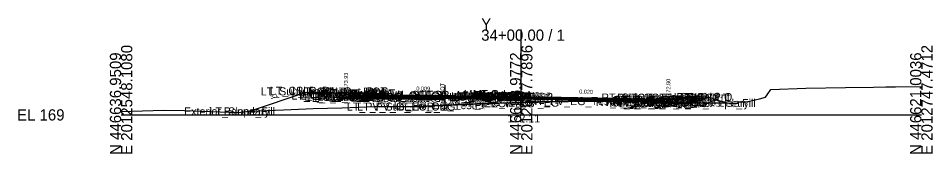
# Model space of a CAD drawing. Extents: x -26 to 3203, y -10 to 9532.
# Drawn here: x 1974.3 to 2202.8, y 7990.3 to 8024.1 of the extents above; entities that cross this region are included whole.
import ezdxf

# ---------------------------------------------------------------- set-up
doc = ezdxf.new("R2010")
doc.units = 0
for name, color, linetype in [('Default', 7, 'Continuous'), ('Exist CMT Pavement', 7, 'Continuous'), ('Exist Cross Section Cell', 7, 'Continuous'), ('Exist XS Center Line Elevation Label', 7, 'Continuous'), ('Exist XS Ground Line', 7, 'Continuous'), ('Prop CMT Conc Surface', 7, 'Continuous'), ('Prop CMT Concrete Structures', 7, 'Continuous'), ('Prop CMT Pvmt Course 1', 7, 'Continuous'), ('Prop CMT Pvmt Course 1 CG', 7, 'Continuous'), ('Prop CMT Pvmt Course 1 Wedge', 7, 'Continuous'), ('Prop CMT Pvmt Course 2', 7, 'Continuous'), ('Prop CMT Pvmt Course 2 Wedge', 7, 'Continuous'), ('Prop CMT Pvmt Course 3', 7, 'Continuous'), ('Prop CMT Pvmt Course 3 Wedge', 7, 'Continuous'), ('Prop CMT Pvmt Surface', 7, 'Continuous'), ('Prop CMT Pvmt Wedge Surface 1', 7, 'Continuous'), ('Prop CMT Pvmt Wedge Surface 2', 7, 'Continuous'), ('Prop CMT Pvmt Wedge Surface 3', 7, 'Continuous'), ('Prop CMT Slope Grass', 7, 'Continuous'), ('Prop CMT Subgrade Earthwork', 7, 'Continuous'), ('Prop XS Hydro Elevations', 7, 'Continuous'), ('Prop XS Label Text', 7, 'Continuous'), ('Prop XS SE Text', 7, 'Continuous'), ('Prop XS Side Slope Text', 7, 'Continuous'), ('Scratch_Level_0', 7, 'Continuous')]:
    doc.layers.add(name, color=color, linetype=linetype)

msp = doc.modelspace()

# ---------------------------------------------------------------- linework, layer by layer
at = {"layer": 'Exist CMT Pavement'}
for points in [[(2115.72, 8003.44), (2097.68, 8003.05)], [(2132.75, 8003.24), (2115.72, 8003.44)], [(2080.92, 8002.42), (2081.73, 8002.44)], [(2081.73, 8002.44), (2092, 8002.89)]]:
    msp.add_lwpolyline(points, dxfattribs=at)
at = {"layer": 'Exist Cross Section Cell'}
for p, q in [((2100, 8000), (2100, 8021.33)), ((2000, 8000), (2100, 8000)), ((2100, 8000), (2200, 8000))]:
    msp.add_line(p, q, dxfattribs=at)
at = {"layer": 'Exist XS Ground Line'}
msp.add_lwpolyline([(2000, 8000.86), (2010.69, 8001.21), (2015.84, 8001.06), (2029.2, 8000.59), (2031.35, 8000.86), (2032.14, 8000.9), (2040.62, 8001.23), (2046.25, 8001.55), (2048.04, 8001.59), (2055.14, 8001.79), (2063.36, 8002.12), (2065.93, 8002.07), (2071.46, 8002.09), (2072.32, 8001.98), (2078.4, 8002.3), (2079.94, 8002.36), (2080.49, 8002.39), (2080.91, 8002.41), (2082.43, 8002.47), (2084.3, 8002.58), (2084.78, 8002.6), (2086.07, 8002.7), (2086.69, 8002.71), (2089.2, 8002.8), (2091.32, 8002.87), (2091.72, 8002.88), (2093.65, 8002.95), (2094.23, 8002.97), (2094.9, 8002.98), (2096.73, 8003.03), (2097.63, 8003.05), (2099.22, 8003.09), (2100, 8003.11), (2100.59, 8003.13), (2101.72, 8003.15), (2103.05, 8003.19), (2104.21, 8003.21), (2105.21, 8003.24), (2106.72, 8003.28), (2108.49, 8003.31), (2109.23, 8003.33), (2109.86, 8003.34), (2111.73, 8003.38), (2114.27, 8003.42), (2116.71, 8003.45), (2117.45, 8003.45), (2119.27, 8003.46), (2121.82, 8003.46), (2122.15, 8003.46), (2124.34, 8003.44), (2124.93, 8003.43), (2126.84, 8003.39), (2128.49, 8003.35), (2129.35, 8003.33), (2130.36, 8003.3), (2131.85, 8003.26), (2133.08, 8003.24), (2134.36, 8003.22), (2135.45, 8003.2), (2136.86, 8003.17), (2138.51, 8003.14), (2139.37, 8003.13), (2141.23, 8003.1), (2141.86, 8003.09), (2143.95, 8003.05), (2144.36, 8003.05), (2146.86, 8003.01), (2148.93, 8003), (2149.46, 8002.99), (2151.93, 8002.95), (2152.41, 8002.92), (2153.69, 8002.85), (2154.41, 8003.28), (2154.89, 8003.3), (2156.33, 8003.29), (2159.52, 8004.02), (2161.08, 8004.43), (2161.46, 8004.98), (2162.42, 8006.38), (2171.11, 8006.64), (2181.06, 8006.88), (2188.08, 8006.97), (2191.1, 8006.99), (2193.51, 8007.03), (2200, 8007.11)], dxfattribs=at)
at = {"layer": 'Prop CMT Conc Surface'}
for points in [[(2051.69, 8005.52), (2046.69, 8005.62)], [(2056.19, 8004.93), (2056.19, 8005.43), (2055.69, 8005.43)], [(2058.19, 8004.99), (2056.19, 8004.93)], [(2134.75, 8003.92), (2136.75, 8003.8)], [(2136.75, 8003.8), (2136.75, 8004.3), (2137.25, 8004.3)], [(2141.25, 8004.39), (2146.25, 8004.49)]]:
    msp.add_lwpolyline(points, dxfattribs=at)
at = {"layer": 'Prop CMT Concrete Structures'}
for points in [[(2046.69, 8005.29), (2046.69, 8005.62)], [(2046.69, 8005.62), (2051.69, 8005.52)], [(2051.69, 8005.52), (2051.69, 8005.19)], [(2051.69, 8005.19), (2046.69, 8005.29)], [(2058.19, 8004.99), (2056.19, 8004.93), (2056.19, 8005.43), (2055.69, 8005.43)], [(2055.69, 8005.43), (2055.69, 8004.43), (2058.19, 8004.41)], [(2058.19, 8004.41), (2058.19, 8004.99)], [(2097.68, 8004.66), (2097.67, 8004.83), (2096.92, 8005.08), (2094.84, 8005.14), (2092.76, 8005.1), (2092.01, 8004.85), (2092, 8004.69)], [(2092, 8004.69), (2097.68, 8004.66)], [(2134.75, 8003.92), (2136.75, 8003.8), (2136.75, 8004.3), (2137.25, 8004.3)], [(2137.25, 8004.3), (2137.25, 8003.28), (2134.75, 8003.33)], [(2134.75, 8003.33), (2134.75, 8003.92)], [(2146.25, 8004.49), (2141.25, 8004.39)], [(2141.25, 8004.39), (2141.25, 8004.05)], [(2141.25, 8004.05), (2146.25, 8004.15)], [(2146.25, 8004.15), (2146.25, 8004.49)]]:
    msp.add_lwpolyline(points, dxfattribs=at)
at = {"layer": 'Prop CMT Pvmt Course 1'}
for points in [[(2092, 8004.69), (2058.19, 8004.99)], [(2058.19, 8004.99), (2058.19, 8004.74)], [(2058.19, 8004.74), (2071.46, 8004.62)], [(2071.46, 8004.62), (2071.46, 8004.75)], [(2071.46, 8004.75), (2092, 8004.56)], [(2080.91, 8004.72), (2080.91, 8004.84)], [(2092, 8004.69), (2097.68, 8004.66)], [(2092, 8004.44), (2092, 8004.69)], [(2092, 8004.44), (2092, 8004.69)], [(2092, 8004.56), (2092, 8004.44), (2092, 8004.44)], [(2097.68, 8004.41), (2092, 8004.44)], [(2097.68, 8004.66), (2134.75, 8003.92)], [(2097.68, 8004.41), (2097.68, 8004.66)], [(2097.68, 8004.66), (2097.68, 8004.41)], [(2132.75, 8003.83), (2097.68, 8004.53)], [(2097.68, 8004.53), (2097.68, 8004.41), (2097.68, 8004.41)], [(2132.75, 8003.71), (2132.75, 8003.83)], [(2134.75, 8003.67), (2133.75, 8003.69)], [(2134.75, 8003.92), (2134.75, 8003.67)]]:
    msp.add_lwpolyline(points, dxfattribs=at)
at = {"layer": 'Prop CMT Pvmt Course 1 CG'}
for points in [[(2058.19, 8004.41), (2055.19, 8004.44), (2054.86, 8004.11)], [(2054.86, 8004.11), (2058.19, 8004.08)], [(2058.19, 8004.08), (2058.19, 8004.41)], [(2134.75, 8003.33), (2137.75, 8003.27), (2138.09, 8002.93)], [(2134.75, 8003), (2134.75, 8003.33)], [(2138.09, 8002.93), (2134.75, 8003)]]:
    msp.add_lwpolyline(points, dxfattribs=at)
at = {"layer": 'Prop CMT Pvmt Course 1 Wedge'}
for points in [[(2071.46, 8004.75), (2071.46, 8004.75)], [(2071.46, 8004.75), (2072.13, 8004.74), (2072.32, 8004.74), (2078.4, 8004.68), (2079.94, 8004.67), (2080.49, 8004.67), (2080.91, 8004.66), (2082.42, 8004.65), (2082.43, 8004.65), (2084.3, 8004.63), (2084.78, 8004.63), (2086.07, 8004.61), (2086.68, 8004.61), (2086.69, 8004.61), (2088.99, 8004.59), (2089.2, 8004.59), (2091.32, 8004.57), (2091.72, 8004.56), (2092, 8004.56)], [(2071.46, 8004.62), (2071.46, 8004.75)], [(2092, 8004.44), (2091.72, 8004.44), (2091.32, 8004.44), (2089.2, 8004.46), (2088.99, 8004.46), (2086.69, 8004.48), (2086.68, 8004.48), (2086.07, 8004.49), (2084.78, 8004.5), (2084.3, 8004.51), (2082.43, 8004.52), (2082.42, 8004.52), (2080.91, 8004.54), (2080.49, 8004.54), (2079.94, 8004.55), (2078.4, 8004.56), (2072.32, 8004.62), (2072.13, 8004.62), (2071.46, 8004.62)], [(2071.46, 8004.62), (2071.46, 8004.62)], [(2092, 8004.56), (2092, 8004.44)], [(2097.68, 8004.41), (2097.68, 8004.53)], [(2097.68, 8004.53), (2099.22, 8004.5), (2100.59, 8004.48), (2101.72, 8004.45), (2103.05, 8004.43), (2104.21, 8004.4), (2105.21, 8004.38), (2106.72, 8004.35), (2108.49, 8004.32), (2109.23, 8004.3), (2109.86, 8004.29), (2111.73, 8004.25), (2113.99, 8004.21), (2114.27, 8004.2), (2116.65, 8004.15), (2116.71, 8004.15), (2117.45, 8004.14), (2119.15, 8004.1), (2119.27, 8004.1), (2121.53, 8004.06), (2121.82, 8004.05), (2122.15, 8004.04), (2124.34, 8004), (2124.93, 8003.99), (2126.84, 8003.95), (2128.49, 8003.92), (2129.35, 8003.9), (2130.36, 8003.88), (2131.85, 8003.85), (2132.75, 8003.83)], [(2133.75, 8003.69), (2133.08, 8003.7), (2131.85, 8003.73), (2130.36, 8003.76), (2129.35, 8003.78), (2128.49, 8003.79), (2126.84, 8003.83), (2124.93, 8003.86), (2124.34, 8003.88), (2122.15, 8003.92), (2121.82, 8003.93), (2121.53, 8003.93), (2119.27, 8003.98), (2119.15, 8003.98), (2117.45, 8004.01), (2116.71, 8004.03), (2116.65, 8004.03), (2114.27, 8004.08), (2113.99, 8004.08), (2111.73, 8004.13), (2109.86, 8004.17), (2109.23, 8004.18), (2108.49, 8004.19), (2106.72, 8004.23), (2105.21, 8004.26), (2104.21, 8004.28), (2103.05, 8004.3), (2101.72, 8004.33), (2100.59, 8004.35), (2099.22, 8004.38), (2097.68, 8004.41)], [(2132.75, 8003.83), (2132.75, 8003.71)]]:
    msp.add_lwpolyline(points, dxfattribs=at)
at = {"layer": 'Prop CMT Pvmt Course 2'}
for points in [[(2071.46, 8004.62), (2058.19, 8004.74)], [(2058.19, 8004.74), (2058.19, 8004.41)], [(2058.19, 8004.41), (2071.46, 8004.29)], [(2071.46, 8004.29), (2071.46, 8004.62)], [(2080.91, 8004.38), (2080.91, 8004.72)], [(2092, 8004.44), (2097.68, 8004.41)], [(2092, 8004.1), (2092, 8004.44)], [(2097.68, 8004.08), (2092, 8004.1)], [(2097.68, 8004.41), (2097.68, 8004.08)], [(2132.75, 8003.37), (2132.75, 8003.71)], [(2133.75, 8003.69), (2134.75, 8003.67)], [(2134.75, 8003.33), (2133.75, 8003.35)], [(2134.75, 8003.67), (2134.75, 8003.33)]]:
    msp.add_lwpolyline(points, dxfattribs=at)
at = {"layer": 'Prop CMT Pvmt Course 2 Wedge'}
for points in [[(2071.46, 8004.62), (2071.46, 8004.62)], [(2071.46, 8004.62), (2072.13, 8004.62), (2072.32, 8004.62), (2078.4, 8004.56), (2079.94, 8004.55), (2080.49, 8004.54), (2080.91, 8004.54), (2082.42, 8004.52), (2082.43, 8004.52), (2084.3, 8004.51), (2084.78, 8004.5), (2086.07, 8004.49), (2086.68, 8004.48), (2086.69, 8004.48), (2088.99, 8004.46), (2089.2, 8004.46), (2091.32, 8004.44), (2091.72, 8004.44), (2092, 8004.44)], [(2071.46, 8004.29), (2071.46, 8004.62)], [(2092, 8004.1), (2091.72, 8004.11), (2091.32, 8004.11), (2089.2, 8004.13), (2088.99, 8004.13), (2086.69, 8004.15), (2086.68, 8004.15), (2086.07, 8004.16), (2084.78, 8004.17), (2084.3, 8004.17), (2082.43, 8004.19), (2082.42, 8004.19), (2080.91, 8004.2), (2080.49, 8004.21), (2079.94, 8004.21), (2078.4, 8004.23), (2072.32, 8004.28), (2072.13, 8004.28), (2071.46, 8004.29)], [(2071.46, 8004.29), (2071.46, 8004.29)], [(2092, 8004.44), (2092, 8004.1)], [(2097.68, 8004.41), (2099.22, 8004.38), (2100.59, 8004.35), (2101.72, 8004.33), (2103.05, 8004.3), (2104.21, 8004.28), (2105.21, 8004.26), (2106.72, 8004.23), (2108.49, 8004.19), (2109.23, 8004.18), (2109.86, 8004.17), (2111.73, 8004.13), (2113.99, 8004.08), (2114.27, 8004.08), (2116.65, 8004.03), (2116.71, 8004.03), (2117.45, 8004.01), (2119.15, 8003.98), (2119.27, 8003.98), (2121.53, 8003.93), (2121.82, 8003.93), (2122.15, 8003.92), (2124.34, 8003.88), (2124.93, 8003.86), (2126.84, 8003.83), (2128.49, 8003.79), (2129.35, 8003.78), (2130.36, 8003.76), (2131.85, 8003.73), (2133.08, 8003.7), (2133.75, 8003.69)], [(2097.68, 8004.08), (2097.68, 8004.41)], [(2133.75, 8003.35), (2133.08, 8003.37), (2131.85, 8003.39), (2130.36, 8003.42), (2129.35, 8003.44), (2128.49, 8003.46), (2126.84, 8003.49), (2124.93, 8003.53), (2124.34, 8003.54), (2122.15, 8003.59), (2121.82, 8003.59), (2121.53, 8003.6), (2119.27, 8003.64), (2119.15, 8003.65), (2117.45, 8003.68), (2116.71, 8003.7), (2116.65, 8003.7), (2114.27, 8003.74), (2113.99, 8003.75), (2111.73, 8003.79), (2109.86, 8003.83), (2109.23, 8003.84), (2108.49, 8003.86), (2106.72, 8003.9), (2105.21, 8003.93), (2104.21, 8003.95), (2103.05, 8003.97), (2101.72, 8004), (2100.59, 8004.02), (2099.22, 8004.04), (2097.68, 8004.08)], [(2132.75, 8003.71), (2132.75, 8003.37)]]:
    msp.add_lwpolyline(points, dxfattribs=at)
at = {"layer": 'Prop CMT Pvmt Course 3'}
for points in [[(2071.46, 8004.29), (2058.19, 8004.41)], [(2058.19, 8004.41), (2058.19, 8004.08)], [(2058.19, 8004.08), (2080.91, 8003.87)], [(2071.46, 8003.96), (2071.46, 8004.29)], [(2080.91, 8004.05), (2080.91, 8004.38)], [(2092, 8004.1), (2097.68, 8004.08)], [(2133.75, 8003.35), (2134.75, 8003.33)], [(2134.75, 8003.33), (2134.75, 8003)], [(2134.75, 8003), (2132.75, 8003.04)]]:
    msp.add_lwpolyline(points, dxfattribs=at)
at = {"layer": 'Prop CMT Pvmt Course 3 Wedge'}
for points in [[(2071.46, 8004.29), (2071.46, 8004.29)], [(2071.46, 8004.29), (2072.13, 8004.28), (2072.32, 8004.28), (2078.4, 8004.23), (2079.94, 8004.21), (2080.49, 8004.21), (2080.91, 8004.2), (2082.42, 8004.19), (2082.43, 8004.19), (2084.3, 8004.17), (2084.78, 8004.17), (2086.07, 8004.16), (2086.68, 8004.15), (2086.69, 8004.15), (2088.99, 8004.13), (2089.2, 8004.13), (2091.32, 8004.11), (2091.72, 8004.11), (2092, 8004.1)], [(2097.68, 8004.08), (2099.22, 8004.04), (2100.59, 8004.02), (2101.72, 8004), (2103.05, 8003.97), (2104.21, 8003.95), (2105.21, 8003.93), (2106.72, 8003.9), (2108.49, 8003.86), (2109.23, 8003.84), (2109.86, 8003.83), (2111.73, 8003.79), (2113.99, 8003.75), (2114.27, 8003.74), (2116.65, 8003.7), (2116.71, 8003.7), (2117.45, 8003.68), (2119.15, 8003.65), (2119.27, 8003.64), (2121.53, 8003.6), (2121.82, 8003.59), (2122.15, 8003.59), (2124.34, 8003.54), (2124.93, 8003.53), (2126.84, 8003.49), (2128.49, 8003.46), (2129.35, 8003.44), (2130.36, 8003.42), (2131.85, 8003.39), (2133.08, 8003.37), (2133.75, 8003.35)], [(2133.75, 8003.23), (2133.08, 8003.24), (2131.85, 8003.26), (2130.36, 8003.3), (2129.35, 8003.33), (2128.49, 8003.35), (2126.84, 8003.39), (2124.93, 8003.43), (2124.34, 8003.44), (2122.15, 8003.46), (2121.82, 8003.46), (2121.53, 8003.46), (2119.27, 8003.46), (2119.15, 8003.46), (2117.45, 8003.45), (2116.71, 8003.45), (2116.65, 8003.45), (2114.27, 8003.42), (2113.99, 8003.41), (2111.73, 8003.38), (2109.86, 8003.34), (2109.23, 8003.33), (2108.49, 8003.31), (2106.72, 8003.28), (2105.21, 8003.24), (2104.21, 8003.21), (2103.05, 8003.19), (2101.72, 8003.15), (2100.59, 8003.13), (2099.22, 8003.09), (2097.68, 8003.05)], [(2132.75, 8003.37), (2132.75, 8003.25)], [(2092, 8002.89), (2091.72, 8002.88), (2091.32, 8002.87), (2089.2, 8002.8), (2088.99, 8002.79), (2086.69, 8002.71), (2086.68, 8002.71), (2086.07, 8002.7), (2084.78, 8002.6), (2084.3, 8002.58), (2082.43, 8002.47), (2082.42, 8002.47), (2080.91, 8002.41), (2080.49, 8002.39), (2079.94, 8002.36), (2078.4, 8002.3), (2072.32, 8001.98), (2072.13, 8001.99), (2071.46, 8002.09)], [(2071.46, 8002.09), (2071.46, 8002.09)]]:
    msp.add_lwpolyline(points, dxfattribs=at)
at = {"layer": 'Prop CMT Pvmt Surface'}
for points in [[(2092, 8004.69), (2058.19, 8004.99)], [(2092, 8004.69), (2097.68, 8004.66)], [(2097.68, 8004.66), (2134.75, 8003.92)]]:
    msp.add_lwpolyline(points, dxfattribs=at)
at = {"layer": 'Prop CMT Pvmt Wedge Surface 1'}
for points in [[(2058.19, 8004.74), (2058.19, 8004.99)], [(2071.46, 8004.62), (2058.19, 8004.74)], [(2092, 8004.56), (2071.46, 8004.75)], [(2071.46, 8004.75), (2071.46, 8004.62)], [(2080.91, 8004.84), (2080.91, 8004.72)], [(2092, 8004.69), (2092, 8004.44), (2092, 8004.44), (2092, 8004.56)], [(2097.68, 8004.66), (2097.68, 8004.41), (2097.68, 8004.41), (2097.68, 8004.53)], [(2097.68, 8004.53), (2132.75, 8003.83)], [(2132.75, 8003.83), (2132.75, 8003.71)], [(2133.75, 8003.69), (2134.75, 8003.67)], [(2134.75, 8003.67), (2134.75, 8003.92)]]:
    msp.add_lwpolyline(points, dxfattribs=at)
at = {"layer": 'Prop CMT Pvmt Wedge Surface 2'}
for points in [[(2058.19, 8004.74), (2058.19, 8004.99)], [(2092, 8004.44), (2058.19, 8004.74)], [(2092, 8004.69), (2092, 8004.44)], [(2097.68, 8004.66), (2097.68, 8004.41)], [(2097.68, 8004.41), (2134.75, 8003.67)], [(2134.75, 8003.67), (2134.75, 8003.92)]]:
    msp.add_lwpolyline(points, dxfattribs=at)
at = {"layer": 'Prop CMT Pvmt Wedge Surface 3'}
for points in [[(2058.19, 8004.41), (2058.19, 8004.99)], [(2092, 8004.1), (2058.19, 8004.41)], [(2092, 8004.69), (2092, 8004.1)], [(2097.68, 8004.66), (2097.68, 8004.08)], [(2097.68, 8004.08), (2134.75, 8003.33)], [(2134.75, 8003.33), (2134.75, 8003.92)]]:
    msp.add_lwpolyline(points, dxfattribs=at)
at = {"layer": 'Prop CMT Slope Grass'}
for points in [[(2055.69, 8005.43), (2046.19, 8005.62), (2031.99, 8000.89)], [(2137.25, 8004.3), (2146.25, 8004.48)], [(2146.25, 8004.48), (2146.75, 8004.49), (2151.33, 8002.96)]]:
    msp.add_lwpolyline(points, dxfattribs=at)
at = {"layer": 'Prop CMT Subgrade Earthwork'}
msp.add_line((2132.75, 8003.24), (2132.75, 8003.04), dxfattribs=at)
for points in [[(2058.19, 8004.08), (2054.86, 8004.11), (2053.49, 8005.48)], [(2080.91, 8003.87), (2058.19, 8004.08)], [(2080.91, 8003.87), (2080.92, 8002.42)], [(2134.75, 8003), (2138.09, 8002.93), (2139.5, 8004.34)], [(2132.75, 8003.04), (2134.75, 8003)]]:
    msp.add_lwpolyline(points, dxfattribs=at)
at = {"layer": 'Prop XS Label Text'}
msp.add_line((2080.91, 8007.41), (2080.91, 8002.41), dxfattribs=at)

# ---------------------------------------------------------------- texts
at = {"layer": 'Default'}
msp.add_text('-', height=0.0001, dxfattribs=at).set_placement((2000, 8000))
at = {"layer": 'Exist Cross Section Cell'}
for s, p in [('Y', (2090, 8021.33)), ('34+00.00 / 1', (2090, 8018.53)), ('EL 169', (1974, 7998.6))]:
    msp.add_text(s, height=2.8, dxfattribs=at).set_placement(p)
for s, p in [('E 2012548.1080', (2002.8, 7990)), ('E 2012647.7896', (2102.8, 7990)), ('E 2012747.4712', (2202.8, 7990)), ('N 446636.9509', (2000, 7990)), ('N 446628.9772', (2100, 7990)), ('N 446621.0036', (2200, 7990))]:
    msp.add_text(s, height=2.8, rotation=90, dxfattribs=at).set_placement(p)
at = {"layer": 'Exist XS Center Line Elevation Label'}
msp.add_text('172.11', height=2, dxfattribs=at).set_placement((2096.56, 7998.11))
at = {"layer": 'Prop XS Hydro Elevations'}
for s, p in [('173.93', (2056.69, 8006.34)), ('172.80', (2137.25, 8004.8))]:
    msp.add_text(s, height=1, rotation=90, dxfattribs=at).set_placement(p)
at = {"layer": 'Prop XS Label Text'}
msp.add_text('E. EOT', height=1, rotation=90, dxfattribs=at).set_placement((2080.81, 8003.43))
at = {"layer": 'Prop XS SE Text'}
for s, rotation, p in [('0.009', 358.9387, (2073.79, 8006.1)), ('0.020', 358.8542, (2114.49, 8005.32))]:
    msp.add_text(s, height=1, rotation=rotation, dxfattribs=at).set_placement(p)
at = {"layer": 'Prop XS Side Slope Text'}
for rotation, p in [(341.5651, (2148.53, 8004.69)), (18.4349, (2037.48, 8003.92))]:
    msp.add_text('3:1', height=1, rotation=rotation, dxfattribs=at).set_placement(p)
at = {"layer": 'Scratch_Level_0'}
for s, p in [('LT_Sub_Trench_Out_DLT', (2034.9, 8004.87)), ('LT_CSLP_Pnt', (2037.19, 8005.02)), ('LT_CG1_Shelf_Out', (2042.56, 8003.84)), ('LT_CG_Top_Face', (2044.27, 8004.83)), ('LT_CG_Top_BOC', (2044.8, 8004.83)), ('LT_CG_Bot_BOC', (2044.83, 8003.83)), ('LT_CG_Top_Gut', (2045.25, 8004.33)), ('LT_Sub_OEOP', (2045.8, 8003.52)), ('LT_Sub_OEOT_CG', (2046.38, 8003.46)), ('LT_CG_Bot_IE', (2048.93, 8003.79)), ('LT_Sub_OEOT', (2049.09, 8003.46)), ('LT_PV2_OEOT', (2049.19, 8004.12)), ('LT_PV3_OEOT', (2049.19, 8003.79)), ('LT_PV1_OEOT', (2049.75, 8004.37)), ('LT_PV2_OEEOP', (2060.77, 8003.89)), ('LT_PV3_OEEOP', (2060.77, 8003.56)), ('LT_PV1_OEEOP', (2061.34, 8004.02)), ('LT_PV2_IEEOP', (2081.95, 8003.51)), ('LT_PV1_IEEOP', (2082.52, 8003.64)), ('LT_PV2_PGL1', (2082.88, 8003.51)), ('LT_PV2_PGL', (2083.21, 8003.51)), ('LT_PV1_PGL', (2083.78, 8003.76)), ('MI_Face In', (2083.9, 8003.93)), ('MI_Top In', (2085.61, 8004.18)), ('MI_Crown', (2087.91, 8004.22)), ('MI_Face Out', (2087.94, 8003.83)), ('MI_Top Out', (2088.15, 8004.08)), ('RT_PV1_IEEOP', (2088.16, 8003.53)), ('MI_Bot Out', (2088.94, 8003.66)), ('RT_PV1_PGL', (2089.42, 8003.66)), ('RT_Shld_O', (2138.79, 8003.48)), ('CSLP_Pnt', (2139.62, 8003.49)), ('LT_Sub_OEEOP', (2060.67, 8003.22)), ('LT_PV_EG_TestPt', (2068.14, 8001.44)), ('LT_PV_IEEOP_EG', (2080.19, 8001.89)), ('LT_PV3_IEEOP', (2081.95, 8003.18)), ('LT_PV3_PGL1', (2082.88, 8003.18)), ('LT_PV3_PGL', (2083.21, 8003.18)), ('LT_PV4_PGL', (2083.21, 8002.84)), ('RT_PV_IEEOP_EG', (2085.83, 8002.05)), ('RT_PV2_IEEOP', (2087.59, 8003.41)), ('RT_PV3_IEEOP', (2087.59, 8003.08)), ('RT_PV2_PGL1', (2088.52, 8003.41)), ('RT_PV3_PGL1', (2088.52, 8003.08)), ('RT_PV2_PGL', (2088.85, 8003.41)), ('RT_PV3_PGL', (2088.85, 8003.08)), ('RT_PV4_PGL', (2088.85, 8002.74)), ('RT_PV_EG_TestPt', (2102.08, 8002.44)), ('RT_PV_Sub_Tie_Out', (2118.63, 8002.23)), ('RT_Sub_Trench_Out_DLT', (2120.02, 8003.34)), ('RT_PV_OEEOP_EG', (2121.25, 8002.23)), ('RT_Sub_OEOT_CG', (2122.07, 8002)), ('RT_Sub_OEEOP', (2122.92, 8002.02)), ('RT_PV2_OEEOP', (2123.01, 8002.69)), ('RT_PV3_OEEOP', (2123.01, 8002.35)), ('RT_PV1_OEEOP', (2123.58, 8002.81)), ('RT_CG_Top_Face', (2123.96, 8003.3)), ('RT_CG1_Shelf_Out', (2124.25, 8002.27)), ('RT_CG_Bot_IE', (2124.62, 8002.33)), ('RT_Sub_OEOT', (2124.78, 8002)), ('RT_PV2_OEOT', (2124.88, 8002.67)), ('RT_PV3_OEOT', (2124.88, 8002.33)), ('RT_CG_Top_Gut', (2124.94, 8002.8)), ('RT_PV1_OEOT', (2125.44, 8002.92)), ('RT_CG_Top_BOC', (2125.49, 8003.3)), ('RT_CG_Bot_BOC', (2125.52, 8002.28)), ('RT_Sub_OEOP', (2128.15, 8001.93)), ('Exterior Boundary', (2135.48, 8001.96)), ('RT_Slope_Fill', (2141.81, 8001.96)), ('Exterior Boundary', (2015.73, 7999.88)), ('LT_Slope_Fill', (2022.11, 7999.88)), ('LT_PV_Sub_Tie_Out', (2056.42, 8001.09)), ('LT_PV_OEEOP_EG', (2059.01, 8001.09))]:
    msp.add_text(s, height=2, dxfattribs=at).set_placement(p)

doc.saveas('drawing.dxf')
